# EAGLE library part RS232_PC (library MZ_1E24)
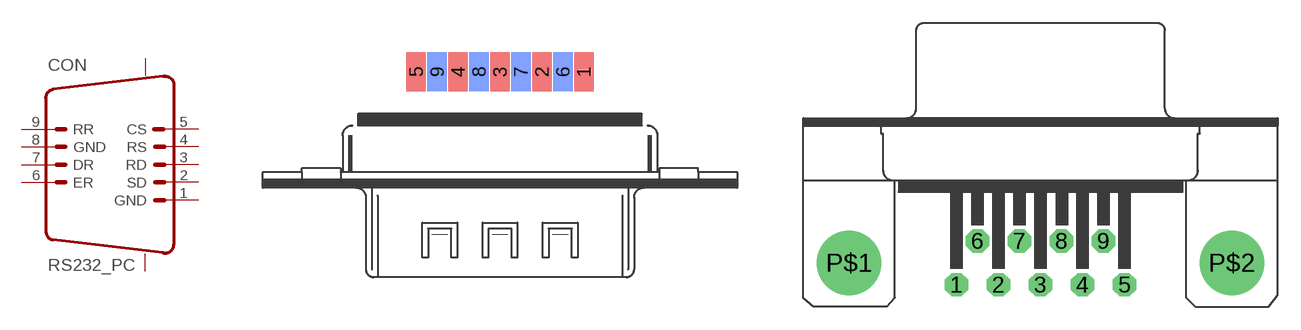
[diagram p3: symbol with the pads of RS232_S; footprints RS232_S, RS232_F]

Designator prefix CON

## RS232_PCSMD  [RS232_S]
1  GND  in
2  SD  in
3  RD  out
4  RS  out
5  CS  pas
6  ER  in
7  DR  out
8  GND  in
9  RR  in

## RS232_PC"  [RS232_F]
1  GND  in
2  SD  in
3  RD  out
4  RS  out
5  CS  pas
6  ER  in
7  DR  out
8  GND  in
9  RR  in
P$1  GND  pas
P$2  GND  pas

## Footprint RS232_S (pad centres in mm)
smd 1.27 x 2.54: 1 5.48,5.48; 2 2.74,5.48; 3 0,5.48; 4 -2.74,5.48; 5 -5.48,5.48
smd 1.27 x 2.54 bottom: 6 4.11,5.48; 7 1.37,5.48; 8 -1.37,5.48; 9 -4.11,5.48

## Footprint RS232_F (pad centres in mm)
drill 1.016 octagon: 1 -5.486,0.794; 2 -2.743,0.794; 3 0,0.794; 4 2.743,0.794; 5 5.486,0.794; 6 -4.115,3.651; 7 -1.372,3.651; 8 1.371,3.651; 9 4.115,3.651
drill 3.2 round: P$1 -12.502,2.223; P$2 12.502,2.223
